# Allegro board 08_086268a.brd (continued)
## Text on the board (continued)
DISPLAY_TOP: FAB NOTES REVISION: NOVEMBER 21 2022 | 8.   IMPEDANCE REQUIREMENTS: IF NO STACKUP IS DEFINED, THE VENDOR IS ALLOWED TO ADJUST THE DIELECTRIC | 13.  PLATING SPECIFICATION: | 1.   DIMENSIONS ARE IN INCHES (EXCEPT WHERE NOTED). | ALL DOCUMENTS & SPECIFICATIONS REFERRED TO BELOW SHOULD BE THE LATEST REVISIONS. | 2.  BOARD MATERIAL:(USE CHECKED ITEMS) | 3.   ALL LAMINATES & BONDING MATERIALS SHOULD BE SELECTED FROM IPC-4101 OR IPC-4103,(TG>170 DEGC TD>300 DEGC) | 4.   REFER TO IPC-6010 SERIES, CLASS 2 FOR FABRICATION. | 5.   REFER TO LAMINATION DIAGRAM FOR OVERALL BOARD THICKNESS, TOLERANCE APPLIES AFTER ALL LAMINATION AND PLATING | 6.   BOW & TWIST NOT TO EXCEED 0.0075 INCHES (0.75%) PER LINEAR INCH AND SHOULD BE MEASURED PER IPC-TM-650, METHOD 2.4.22. | 7.   ACCEPTABILITY PER ADI SPECIFICATION TST00115. | 9.   FILLET OPTIONS TO ENHANCE RELIABILITY AT PAD JUNCTIONS WHERE SPACING PERMITS. | 10.  THIEVING: | 11.  LAYER TO LAYER REGISTRATION SHALL BE WITHIN 0.003 INCHES. | 12.  DRILL SIZES ARE FINISHED HOLE SIZES. ALL HOLES SHALL BE LOCATED WITHIN 0.005 INCHES DTP,UNLESS SPECIFIED. | 14.  SURFACE FINISH: | 15.  SOLDERMASK: | 16.  APPLY SILKSCREEN TO BOTH SIDES USING A NON-CONDUCTIVE, EPOXY BASED INK PER ARTWORK. | (X) WHITE | ( ) OTHER | PROCESSES. FINISHED THICKNESS MEASURED FROM TOP COPPER TO BOTTOM COPPER. | ( )  ISOLA 370HR OR S1000-2 OR IT180 OR EQUIVALENT | ( )  ISOLA-FR408HR OR EQUIVALENT | ( )  ISOLA IS410 | ( )  MEGTRON 6 | ( )  NELCO-4000-13 | ( )  ROGERS 4350B | ( ) ROGERS 3003 | ( ) ARLON 85N | ( ) EM370D | (X)  OTHER NANYA NP-175 TL OR EQUIVALENT | ( ) FILLETS ALLOWED | (X) FILLETS NOT ALLOWED | ( ) VENDOR MAY ADD THIEVING TO COMPENSATE FOR LOW COPPER DENSITY AREAS MAINTAINING A MINIMUM | ( ) VENDOR MAY NOT ADD THIEVING TO COMPENSATE FOR LOW COPPER DENSITY AREAS. | (X) LPI | ( ) OTHER_________ | COLOR | (X) GREEN | HINDER PROPER SOLDER WICKING. BARREL RELIEF ON SOLDERMASK ALLOWED IN UNFILLED VIA IN PAD HOLES. | (X) REFER TO LAMINATION DIAGRAM FOR FINISHED COPPER WEIGHT/THICKNESS REQUIRMENTS | (X) IMMERSION GOLD (ENIG) 1.58-3.94 MICRO INCHES OVER 118-236 MICRO INCHES MIN. OF ELECTROLESS NICKEL PER IPC-4552 | ( ) OSP (ORGANIC SOLDERABILITY PRESERVATIVE) | ( ) IMMERSION SILVER | ( ) SOFT WIRE BONDABLE GOLD 30-50 MICRO INCHES OF SOFT WIRE | ( ) EDGE CONNECTOR FINGERS ARE TO BE PLATED WITH 100 MICRO-INCHES(.0001") OF LOW STRESS | THICKNESS & TRACE WIDTHS TO MEET THE IMPEDANCE REQUIREMENT. IF SPECIFIED, THE VENDOR MUST | TRACE WIDTH & SPACING THAT IMPACT THE REQUIREMENTS MUST HAVE WRITTEN APPROVAL FROM ADI. | MINIMUM BARREL PLATING OF 0.001 INCHES. PLATED HOLES SHALL NOT BE ROUGH OR IRREGULAR SO AS TO | SOLDERMASK OVER BARE COPPER OR BARE GOLD (BOTH SIDES) TO MEET IPC-SM-840. | IF PRESENT,DO NOT MODIFY SOLDERMASK DEFINED PADS (MASK OPENINGS LESS THAN COPPER PAD) WITHOUT APPROVAL. | MEET THE REQUIREMENTS LISTED IN THE IMPEDANCE TABLE. ANY ADJUSTMENT MADE TO THE DEFINED STACKUP, | UL FLAMMABILITY RATING 94V-0. BOARD MATERIAL & CONSTRUCTION SHALL MEET THE REQUIREMENTS OF UL796/UL796F. | BONDABLE GOLD OVER 100-150 MICRO INCHES OF NICKEL | NICKEL UNDER 30 MICRO-INCHES (.00003') OF GOLD | 0.100 INCH CLEARANCE FROM ALL COPPER FEATURES, | THE STARTING COPPER WEIGHT/THICKNESS CAN VARY AS LONG AS THE FINISHED COPPER | WEIGHT/THICKNESS IS NOT LESS THAN THE SPECIFIED VALUE. | UNLESS OTHERWISE SPECIFIED | HOMOGENOUS MATERIALS IN THIS BOARD SHALL BE COMPLAINT WITH THE EU DIRECTIVE 2002/95/EC | WORKMANSHIP SHALL CONFORM TO IPC-A-600, CLASS 2. | 21.  INTENTIONAL SHORTS: | 17.  FINAL ELECTRICAL TEST TO BE PERFORMED USING PROVIDED IPC-D-356A NETLIST OR ODB++ FORMAT FILE. | 22.  PEMNUTS: | 23.  MANUFACTURER TO ETCH/STAMP WITH PERMANENT NON-CONDUCTIVE INK | ON SECONDARY SIDE UNLESS OTHERWISE SPECIFIED: | 18.  A TIME DOMAIN REFLECTOMETER REPORT (TDR) FOR EACH IMPEDANCE CONTROLLED LAYER & A CERTIFICATE | 19.  IF PRESENT, ALL BLIND/BURIED VIAS WITH AN ASPECT RATIO <1:1 TO BE PLATED SHUT WITH COPPER WHEN | 20.  FOR VIA FILL INFORMATION REFER TO DRILL CHART: | 25. PANELIZATION: | 27.  MINIMUM DESIGN LINE WIDTH IS .008 INCH. | 28.  MINIMUM DESIGN LINE SPACING IS .006 INCH. | IS ACCEPTABLE, ALL OTHER INSTANCES MUST BE REPORTED. | IF AN INTENTIONAL SHORT REPORT IS SUPPLIED AND DOES NOT MATCH THE FAB DATA THEN | THE PCB SHALL HAVE A VERIFICATION STAMP. | (X)  NON-CONDUCTIVE EPOXY FILL ALL 0.1524MM, 0.3048MM AND 0.2032MM DRILLED VIAS. | ( )  COPPER FILL ALL 0.XXXX INCHES DRILLED VIAS | ( ) PEMNUTS TO BE INSTALLED BY FABRICATOR | ( ) PEMNUTS NOT TO BE INSTALLED BY FABRICATOR | (X) NOT APPLICABLE | USED AS VIA-IN-PAD OR AS A STACKED VIA. BLIND/BURIED VIAS WITH AN ASPECT RATIO >1:1 TO BE FILLED | A. UL CODE-FLAMMABILITY RATING FOR THOSE APPROVED MATERIALS(IF APPLICABLE) | B. DATE CODE | C. LOT NUMBER | D. MANUFACTURER LOGO | BOARDS TO BE SHIPPED IN ARRAY AND KEPT INTACT | PANEL TO BE SUBJECTED TO CUSTOMERS APPROVAL | PANEL SOLDER PASTE STENCIL GERBER TO BE PROVIDED TO ANALOG | CAN'T BE PERFORMED BECAUSE THE TRACE LENGTH IS TOO SHORT ON THE OUTER LAYERS AT THE PIN ESCAPES | ADI APPROVAL IS REQUIRED. | OF COMPLIANCE SHALL BE PROVIDED BY VENDOR AT TIME OF SHIPMENT. INSTANCES WHERE TDR TESTING | WITH NON-CONDUCTIVE EPOXY. | NOTES: | TOOLING: | FINISH: | MATERIAL: | TESTING: | MISCELLANEOUS:
DIMENSION: LABEL PLACEMENT INFORMATION | HALF SIZE LABELS ARE | AVAILABLE IN THE LIBRARY | PLACE WHEELIE BIN LOGO | TO SUIT THE LAYOUT. | PLACE ROHS COMPLIANT LOGO | TO SUIT THE LAYOUT OR | DELETE IF NOT REQ'D. | PLACE CHINA ROHS COMPLIANT | LOGO TO SUIT THE LAYOUT OR | 1.THE BOARD SIZE CAN BE ADJUSTED TO SUIT THE APPLICATION. | 2.THE MOUNTING HOLES CAN BE MOVED/REMOVED TO SUIT THE APPLICATION. | 3.THE FIDUCIALS CAN BE MOVED TO SUIT THE APPLICATION. | 4.ADJUST THE DIMENSIONS TO SUIT THE APPLICATION. | 5.ADD THE CORRECT LAYER STACKUP ON FAB2 BASED ON THE NO OF LAYERS ON THE PCB. | 6.THE ROHS COMPLIANT AND WHEELIE BIN LOGO'S CAN BE MOVED TO THE DESIRED LOCATION. | HALF SIZE VERSIONS OF THE LABELS ARE AVAILABLE IN THE LIBRARY. | NOTES FOR TEMPLATE USAGE. | GENERIC D-SIZE TEMPLATE BR-067706A
BODY_CENTER: L2-L6 | L3-L6 | L5-L8 | L4-L9
User.11: A | SCALE: 10:1
User.12: SCALE: 10:1
User.17: L2 | 08-      -07
User.18: L3 | 08-      -08
User.19: L4 | 08-      -09
User.20: L5 | 08-      -10
User.22: Champs-Tech PN | CHAMPS TECHNOLOGIES | UNLESS OTHERWISE INDICATED | E Core | I Bar | No. | E | DRAWN | CHKD | APPR | SIGN | DESCRIPTION | DATE | Customer | Part #: | SIZE | REVISIONS | SCALE | ISSUE | REV | THIRD ANGLE PROJECTION | TOLERANCES/UNITS in MM | 1/13/25 | EE14/8.2/14A | 3:1 | B | 00 | .XXX | .XX | .X | ANGLE | A | C | D | F | 1 | 2 | 3 | 4 | 5 | 6 | 7 | 8 | Proprietary & Confidential. Copyright 2005-2025 Champs Technologies LLC. All rights reserved. It is forbidden to copy or use for any purpose without our WRITTEN permission | 4.40 | [.17] | 14.00 | [.55] | 1.50 | [.06] | 3.00 | [.12] | 1.70 | [.07]
User.38: L6 | 08-      -11
User.39: L7 | 08-      -12
User.40: L8 | 08-      -13
User.41: L9 | 08-      -14
User.42: 2
User.43: 3
User.44: 4
User.45: SEE FAB NOTES#20 | 5 | 6 | 7 | 8 | FIGURE | SIZE | 0.1524 | 0.3048 | 0.2032 | 0.4064 | 1.0922 | DRILL CHART: L2 to L3 | DRILL CHART: L3 to L8 | DRILL CHART: L4 to L5 | DRILL CHART: L6 to L7 | DRILL CHART: L8 to L9 | DRILL CHART: L9 to BOTTOM | DRILL CHART: TOP to BOTTOM | DRILL CHART: TOP to L2 | FINISHED HOLES IN MILLIMETERS | PLATED | QTY | 100 | 3 | 32 | 39 | 9 | 97 | 1 | 13 | 50 | 57 | 62 | 63 | 2 | 4 | 68 | 159 | 45 | 60 | 73 | 150 | TOLERANCE/NOTES | TOTAL HOLES:
